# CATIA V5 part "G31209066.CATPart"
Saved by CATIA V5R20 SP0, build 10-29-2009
Part number: G31214066
Revision: 4
Definition: design
Nomenclature: G31214066
Source: made
Description: NOT SPECIFIED
Bounding box of the stored display mesh (mm): x -5 to 66, y -8 to 8, z -8 to 8
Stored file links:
  C:\Users\Raffaele\Desktop\3D X SITO CF\BOLEX\23-BUSH REF 312\G31209066.CATPart

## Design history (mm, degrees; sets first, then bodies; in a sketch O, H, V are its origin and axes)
Body1 "MANIFOLD_SOLID_BREP #14627" (main body)
  Solid1: solid without history
Body2 "MANIFOLD_SOLID_BREP #14770"
  Solid2: solid without history
Body3 "MANIFOLD_SOLID_BREP #14913"
  Solid3: solid without history
Body4 "MANIFOLD_SOLID_BREP #15056"
  Solid4: solid without history
Body5 "MANIFOLD_SOLID_BREP #15199"
  Solid5: solid without history
Body6 "MANIFOLD_SOLID_BREP #15344"
  Solid6: solid without history
Body7 "MANIFOLD_SOLID_BREP #15489"
  Solid7: solid without history
Body8 "MANIFOLD_SOLID_BREP #15634"
  Solid8: solid without history
Body9 "MANIFOLD_SOLID_BREP #15779"
  Solid9: solid without history
Body10 "MANIFOLD_SOLID_BREP #15924"
  Solid10: solid without history
Body11 "MANIFOLD_SOLID_BREP #16069"
  Solid11: solid without history
Body12 "MANIFOLD_SOLID_BREP #16214"
  Solid12: solid without history
Body13 "MANIFOLD_SOLID_BREP #16359"
  Solid13: solid without history
Body14 "MANIFOLD_SOLID_BREP #16504"
  Solid14: solid without history
Body15 "MANIFOLD_SOLID_BREP #16649"
  Solid15: solid without history
Body16 "MANIFOLD_SOLID_BREP #16794"
  Solid16: solid without history
Body17 "MANIFOLD_SOLID_BREP #16939"
  Solid17: solid without history
Body18 "MANIFOLD_SOLID_BREP #17086"
  Solid18: solid without history
Body19 "MANIFOLD_SOLID_BREP #17233"
  Solid19: solid without history
Body20 "MANIFOLD_SOLID_BREP #17380"
  Solid20: solid without history
Body21 "MANIFOLD_SOLID_BREP #17527"
  Solid21: solid without history
Body22 "MANIFOLD_SOLID_BREP #17674"
  Solid22: solid without history
Body23 "MANIFOLD_SOLID_BREP #17821"
  Solid23: solid without history
Body24 "MANIFOLD_SOLID_BREP #17966"
  Solid24: solid without history
Body25 "MANIFOLD_SOLID_BREP #18111"
  Solid25: solid without history
Body26 "MANIFOLD_SOLID_BREP #18256"
  Solid26: solid without history
Body27 "MANIFOLD_SOLID_BREP #18401"
  Solid27: solid without history
Body28 "MANIFOLD_SOLID_BREP #18546"
  Solid28: solid without history
Body29 "MANIFOLD_SOLID_BREP #18691"
  Solid29: solid without history
Body30 "MANIFOLD_SOLID_BREP #18838"
  Solid30: solid without history
Body31 "MANIFOLD_SOLID_BREP #18983"
  Solid31: solid without history
Body32 "MANIFOLD_SOLID_BREP #19128"
  Solid32: solid without history
Body33 "MANIFOLD_SOLID_BREP #19273"
  Solid33: solid without history
Body34 "MANIFOLD_SOLID_BREP #19418"
  Solid34: solid without history
Body35 "MANIFOLD_SOLID_BREP #19563"
  Solid35: solid without history
Body36 "MANIFOLD_SOLID_BREP #19708"
  Solid36: solid without history
Body37 "MANIFOLD_SOLID_BREP #19851"
  Solid37: solid without history
Body38 "MANIFOLD_SOLID_BREP #19994"
  Solid38: solid without history
Body39 "MANIFOLD_SOLID_BREP #20139"
  Solid39: solid without history
Body40 "MANIFOLD_SOLID_BREP #20284"
  Solid40: solid without history
Body41 "MANIFOLD_SOLID_BREP #20429"
  Solid41: solid without history
Body42 "MANIFOLD_SOLID_BREP #20574"
  Solid42: solid without history
Body43 "MANIFOLD_SOLID_BREP #20719"
  Solid43: solid without history
Body44 "MANIFOLD_SOLID_BREP #20864"
  Solid44: solid without history
Body45 "MANIFOLD_SOLID_BREP #21011"
  Solid45: solid without history
Body46 "MANIFOLD_SOLID_BREP #21156"
  Solid46: solid without history
Body47 "MANIFOLD_SOLID_BREP #21301"
  Solid47: solid without history
Body48 "MANIFOLD_SOLID_BREP #21446"
  Solid48: solid without history
Body49 "MANIFOLD_SOLID_BREP #21591"
  Solid49: solid without history
Body50 "MANIFOLD_SOLID_BREP #21736"
  Solid50: solid without history
Body51 "MANIFOLD_SOLID_BREP #21881"
  Solid51: solid without history
Body52 "MANIFOLD_SOLID_BREP #22026"
  Solid52: solid without history
Body53 "MANIFOLD_SOLID_BREP #22171"
  Solid53: solid without history
Body54 "MANIFOLD_SOLID_BREP #22316"
  Solid54: solid without history
Body55 "MANIFOLD_SOLID_BREP #22461"
  Solid55: solid without history
Body56 "MANIFOLD_SOLID_BREP #22606"
  Solid56: solid without history
Body57 "MANIFOLD_SOLID_BREP #22751"
  Solid57: solid without history
Body58 "MANIFOLD_SOLID_BREP #22898"
  Solid58: solid without history
Body59 "MANIFOLD_SOLID_BREP #23041"
  Solid59: solid without history
Body60 "MANIFOLD_SOLID_BREP #23184"
  Solid60: solid without history
Body61 "MANIFOLD_SOLID_BREP #23329"
  Solid61: solid without history
Body62 "MANIFOLD_SOLID_BREP #23474"
  Solid62: solid without history
Body63 "MANIFOLD_SOLID_BREP #23619"
  Solid63: solid without history
Body64 "MANIFOLD_SOLID_BREP #23764"
  Solid64: solid without history
Body65 "MANIFOLD_SOLID_BREP #23909"
  Solid65: solid without history
Body66 "MANIFOLD_SOLID_BREP #24054"
  Solid66: solid without history
Body67 "MANIFOLD_SOLID_BREP #24197"
  Solid67: solid without history
Body68 "MANIFOLD_SOLID_BREP #24340"
  Solid68: solid without history
Body69 "MANIFOLD_SOLID_BREP #24485"
  Solid69: solid without history
Body70 "MANIFOLD_SOLID_BREP #24630"
  Solid70: solid without history
Body71 "MANIFOLD_SOLID_BREP #24775"
  Solid71: solid without history
Body72 "MANIFOLD_SOLID_BREP #24920"
  Solid72: solid without history
Body73 "MANIFOLD_SOLID_BREP #25065"
  Solid73: solid without history
Body74 "MANIFOLD_SOLID_BREP #25210"
  Solid74: solid without history
Body75 "MANIFOLD_SOLID_BREP #25357"
  Solid75: solid without history
Body76 "MANIFOLD_SOLID_BREP #25502"
  Solid76: solid without history
Body77 "MANIFOLD_SOLID_BREP #25647"
  Solid77: solid without history
Body78 "MANIFOLD_SOLID_BREP #25792"
  Solid78: solid without history
Body79 "MANIFOLD_SOLID_BREP #25937"
  Solid79: solid without history
Body80 "MANIFOLD_SOLID_BREP #26082"
  Solid80: solid without history
Body81 "MANIFOLD_SOLID_BREP #26227"
  Solid81: solid without history
Body82 "MANIFOLD_SOLID_BREP #26372"
  Solid82: solid without history
Body83 "MANIFOLD_SOLID_BREP #26517"
  Solid83: solid without history
Body84 "MANIFOLD_SOLID_BREP #26662"
  Solid84: solid without history
Body85 "MANIFOLD_SOLID_BREP #26807"
  Solid85: solid without history
Body86 "MANIFOLD_SOLID_BREP #26952"
  Solid86: solid without history
Body87 "MANIFOLD_SOLID_BREP #27097"
  Solid87: solid without history
Body88 "MANIFOLD_SOLID_BREP #27244"
  Solid88: solid without history
Body89 "MANIFOLD_SOLID_BREP #27387"
  Solid89: solid without history
Body90 "MANIFOLD_SOLID_BREP #27530"
  Solid90: solid without history
Body91 "MANIFOLD_SOLID_BREP #27675"
  Solid91: solid without history
Body92 "MANIFOLD_SOLID_BREP #27820"
  Solid92: solid without history
Body93 "MANIFOLD_SOLID_BREP #27965"
  Solid93: solid without history
Body94 "MANIFOLD_SOLID_BREP #28110"
  Solid94: solid without history
Body95 "MANIFOLD_SOLID_BREP #28255"
  Solid95: solid without history
Body96 "MANIFOLD_SOLID_BREP #28400"
  Solid96: solid without history
Body97 "MANIFOLD_SOLID_BREP #28543"
  Solid97: solid without history
Body98 "MANIFOLD_SOLID_BREP #28686"
  Solid98: solid without history
Body99 "MANIFOLD_SOLID_BREP #28831"
  Solid99: solid without history
Body100 "MANIFOLD_SOLID_BREP #28976"
  Solid100: solid without history
Body101 "MANIFOLD_SOLID_BREP #29121"
  Solid101: solid without history
Body102 "MANIFOLD_SOLID_BREP #29266"
  Solid102: solid without history
Body103 "MANIFOLD_SOLID_BREP #29411"
  Solid103: solid without history
Body104 "MANIFOLD_SOLID_BREP #29556"
  Solid104: solid without history
Body105 "MANIFOLD_SOLID_BREP #29703"
  Solid105: solid without history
